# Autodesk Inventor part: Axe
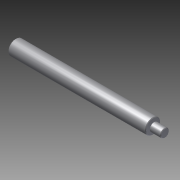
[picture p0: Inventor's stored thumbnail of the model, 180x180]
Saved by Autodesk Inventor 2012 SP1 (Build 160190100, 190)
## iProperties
Created: 2012-06
Part Number: Axe
Material: Default
Document SubType Name: Modeling
Designer: Bruno
Density: 1 g/cm^3
Author: Bruno
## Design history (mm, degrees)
sketch "Esquisse1"
  geometry: L1 (80.033, 4.305)-(80.033, 1); L2 (81.033, 1.805)-(81.033, -0.038); L3 (80.033, -0.038)-(81.033, -0.038); L4 (-48.474, -2.195)-(91.078, -2.195); L5 (-48.474, 3.805)-(-47.474, 4.805); L6 (-48.474, -2.195)-(-48.474, 3.805); L7 (-47.474, 4.805)-(79.533, 4.805); L8 (80.033, 1)-(80.033, -0.038); L9 (81.033, 1.805)-(90.578, 1.805); L10 (91.078, 1.305)-(91.078, -2.195); L11 (91.078, 1.305)-(90.578, 1.805); L12 (80.033, 4.305)-(79.533, 4.805); 2 further points
  constraints: 24 end point, 6 perpendicular, 4 point on line
  dimensions: "d31" = 0.5 distance of L10.start point (91.078, 1.805); "d32" = 0.5 distance of L9.end point (91.078, 1.805) (= d31); "d40" = 7 distance between parallel lines of L7 L4; "d43" = 4 distance between parallel lines of L4 L9; "d46" = 1 horizontal distance of L5.end L5.start; "d47" = 1 horizontal distance of L5.end L5.start; "d48" = 0.5 distance of L1.start point (80.033, 4.805); "d49" = 0.5 distance of L7.end point (80.033, 4.805) (= d48)
revolve "Révolution1" sketch "Esquisse1" stored, may be unused: angle "d7" = 90 deg
sketch "Esquisse3"
  geometry: C1 r 6 at (0, 0) reference; 1 further point
  constraints: 1 coincident
hole "Perçage2" sketch "Esquisse3" at (0, 0) diameter "d33" = 4.917; stored, may be unused: countersink angle "d37" = 90 deg, drill point angle "d39" = 118 deg; dims "d34" = 10, "d35" = 4, "d36" = 2, "d38" = 15
node "Solide1"
